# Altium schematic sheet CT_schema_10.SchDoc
size 274 x 160 mm
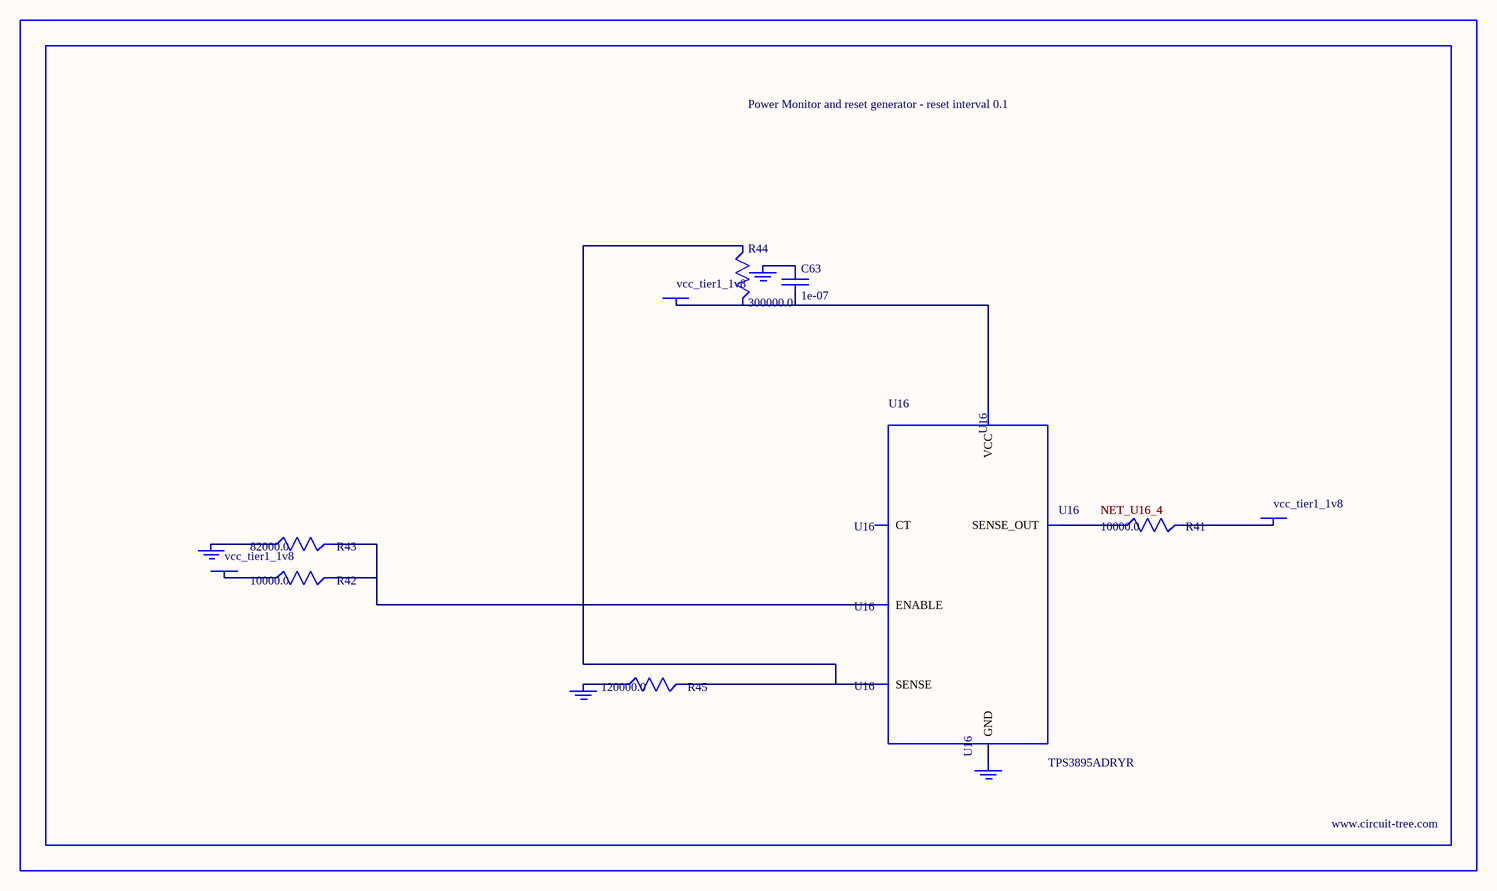
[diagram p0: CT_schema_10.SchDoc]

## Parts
BORDER9  (no value)
C63  1e-07  [C0402]
GND_INSTANCE_9_0  (no value)
GND_INSTANCE_9_1  (no value)
GND_INSTANCE_9_2  (no value)
GND_INSTANCE_9_3  (no value)
POWER_INSTANCE_9_0  vcc_tier1_1v8
POWER_INSTANCE_9_1  vcc_tier1_1v8
POWER_INSTANCE_9_2  vcc_tier1_1v8
R41  10000.0  [R0603]
R42  10000.0  [R0603]
R43  82000.0  [R0603]
R44  300000.0  [R0603]
R45  120000.0  [R0603]
U16  TPS3895ADRYR  [SON-6]

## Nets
NetC63_1: C63.1 GND_INSTANCE_9_2.0(GND)
NetC63_2: C63.2 POWER_INSTANCE_9_2.0(PWR) R44.2 U16.6(VCC)
NetGND_INSTANCE_9_0_0: GND_INSTANCE_9_0.0(GND) R43.1
NetGND_INSTANCE_9_1_0: GND_INSTANCE_9_1.0(GND) R45.1
NetGND_INSTANCE_9_3_0: GND_INSTANCE_9_3.0(GND) U16.2(GND)
NetPOWER_INSTANCE_9_0_0: POWER_INSTANCE_9_0.0(PWR) R42.1
NetPOWER_INSTANCE_9_1_0: POWER_INSTANCE_9_1.0(PWR) R41.2
NetR41_1: R41.1 U16.4(SENSE_OUT)
NetR42_2: R42.2 R43.2 U16.1(ENABLE)
NetR44_1: R44.1 R45.2 U16.3(SENSE)

Not connected (* = marked no-connect by the designer): U16 5(CT)

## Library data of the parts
BORDER9 = BORDER_PAGE9
C63 = C0402C104K3RACTU
GND_INSTANCE_9_0-GND_INSTANCE_9_3 = GND
POWER_INSTANCE_9_0-POWER_INSTANCE_9_2 = PWR
R41 R42 = RC0603JR-0710KL
R43 = RC0603JR-0782KL
R44 = RC0603JR-07300KL
R45 = RC0603JR-07120KL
